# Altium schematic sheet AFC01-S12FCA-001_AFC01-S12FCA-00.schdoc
size 127 x 99 mm
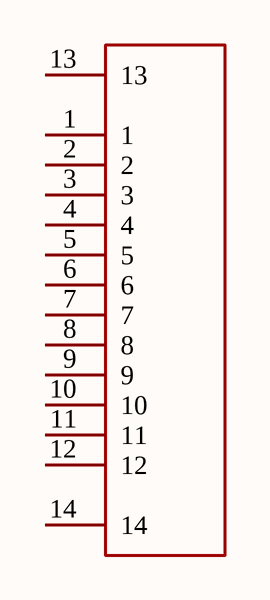
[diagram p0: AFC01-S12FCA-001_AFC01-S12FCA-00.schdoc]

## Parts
FPC?  AFC01-S12FCA-00  [FPC-SMD_AFC01-S12FCA-00]  (value not drawn)

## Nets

Not connected (* = marked no-connect by the designer): FPC? 1 2 3 4 5 6 7 8 9 10 11 12 13 14

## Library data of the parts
FPC? = AFC01-S12FCA-00: Manufacturer: JS(钜硕电子); Add into BOM: yes; Locking Feature: 翻盖式; Number of Contacts: 12P; Pitch: 0.5mm; FFC, FCB Thickness: 0.3mm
